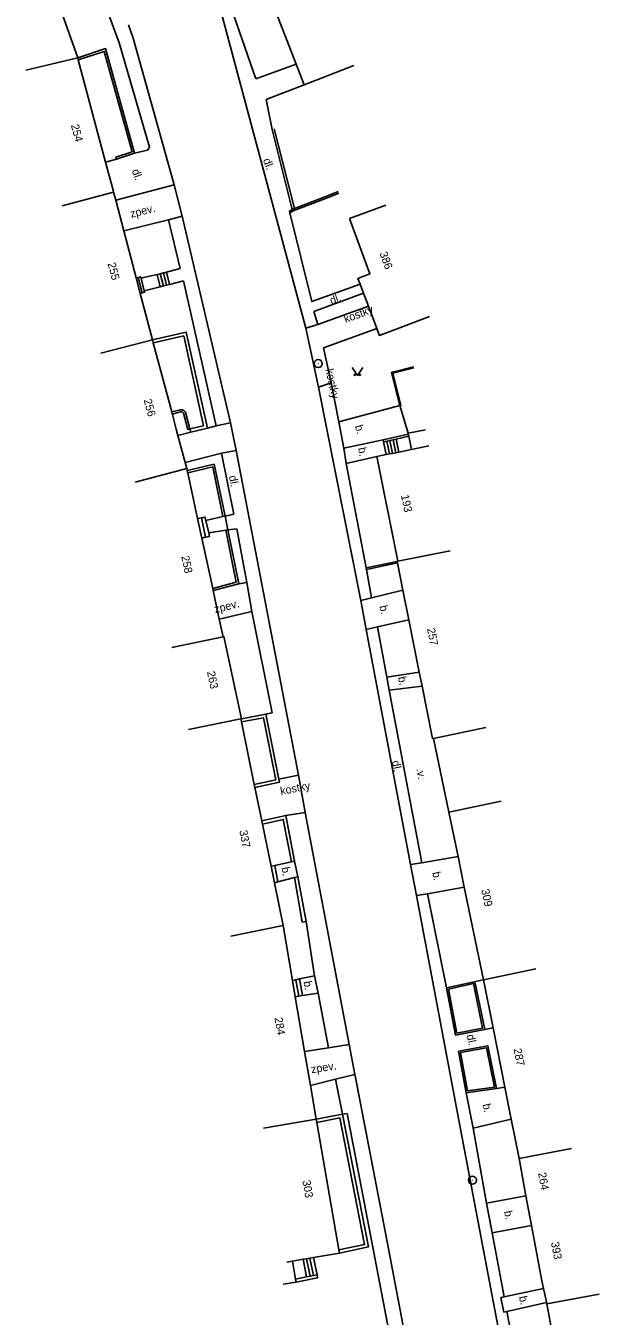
# Model space of a CAD drawing. Extents: x -582162 to -561283, y -1187583 to -1183539.
# Drawn here: x -578230.4 to -578176.6, y -1186277.6 to -1186156.7 of the extents above; entities that cross this region are included whole.
import ezdxf

# ---------------------------------------------------------------- set-up
doc = ezdxf.new("R2010")
doc.units = 0
for name, color, linetype in [('Vrstva 1', 7, 'Continuous'), ('Vrstva 10', 7, 'Continuous'), ('Vrstva 14', 7, 'Continuous'), ('Vrstva 3', 7, 'Continuous'), ('Vrstva 4', 7, 'Continuous'), ('Vrstva 6', 7, 'Continuous'), ('Vrstva 9', 7, 'Continuous')]:
    doc.layers.add(name, color=color, linetype=linetype)

# ---------------------------------------------------------------- blocks, each defined once
blk = doc.blocks.new('1.079')
at = {"layer": 'Vrstva 1'}
for radius in [0.75, 0.001]:
    blk.add_circle((0, -0.001), radius, dxfattribs=at)
blk = doc.blocks.new('3.140')
at = {"layer": 'Vrstva 1'}
blk.add_lwpolyline([(-1, 1.5), (0, 0), (1, 1.5)], dxfattribs=at)
for centre in [(-0.5, 0.1), (0.5, 0.1)]:
    blk.add_circle(centre, 0.1, dxfattribs=at)

msp = doc.modelspace()

# ---------------------------------------------------------------- linework, layer by layer
at = {"layer": 'Vrstva 10'}
for points in [[(-578220.73, -1186156.59), (-578220.31, -1186157.83)], [(-578205.02, -1186160.27), (-578208.79, -1186161.64)], [(-578218.76, -1186168.06), (-578218.95, -1186168.32), (-578220.16, -1186168.61)], [(-578221.86, -1186169.16), (-578222.88, -1186169.45)], [(-578221.94, -1186173.01), (-578216.47, -1186171.59)], [(-578205.62, -1186174.2), (-578205.66, -1186174.04), (-578205.39, -1186173.88)], [(-578199.04, -1186180.88), (-578203.56, -1186182.53), (-578205.62, -1186174.2)], [(-578216.99, -1186174.85), (-578221.18, -1186175.88)], [(-578215.71, -1186174.52), (-578216.99, -1186174.85)], [(-578220.02, -1186180.31), (-578219.83, -1186180.26)], [(-578219.83, -1186180.26), (-578219.6, -1186180.2), (-578219.56, -1186180.34)], [(-578219.83, -1186180.26), (-578219.46, -1186181.71)], [(-578218.05, -1186179.97), (-578219.05, -1186180.2), (-578219.56, -1186180.34)], [(-578217.76, -1186179.91), (-578218.05, -1186179.97)], [(-578217.76, -1186181.13), (-578218.05, -1186179.97)], [(-578217.46, -1186179.84), (-578217.76, -1186179.91)], [(-578217.47, -1186181.06), (-578217.76, -1186179.91)], [(-578217.17, -1186179.77), (-578217.26, -1186179.8), (-578217.46, -1186179.84)], [(-578217.18, -1186180.99), (-578217.46, -1186179.84)], [(-578215.9, -1186179.41), (-578217.17, -1186179.77)], [(-578216.89, -1186180.92), (-578217.17, -1186179.77)], [(-578219.56, -1186180.34), (-578219.27, -1186181.5)], [(-578219.27, -1186181.5), (-578219.23, -1186181.65), (-578219.46, -1186181.71)], [(-578217.76, -1186181.13), (-578219.27, -1186181.5)], [(-578217.47, -1186181.06), (-578217.76, -1186181.13)], [(-578217.18, -1186180.99), (-578217.47, -1186181.06)], [(-578216.89, -1186180.92), (-578217.18, -1186180.99)], [(-578215.57, -1186180.59), (-578216.89, -1186180.92)], [(-578219.46, -1186181.71), (-578219.64, -1186181.76)], [(-578203.01, -1186184.68), (-578203.36, -1186183.46), (-578198.72, -1186181.73)], [(-578198.26, -1186182.94), (-578203.01, -1186184.68)], [(-578203.01, -1186184.68), (-578204.13, -1186185.02)], [(-578197.46, -1186185.06), (-578202.45, -1186186.87), (-578201.74, -1186190.14)], [(-578195.97, -1186189.24), (-578196, -1186189.14)], [(-578201.74, -1186190.14), (-578202.93, -1186190.53)], [(-578201.74, -1186190.14), (-578201.03, -1186193.81)], [(-578195.31, -1186192.26), (-578201.03, -1186193.81)], [(-578194.54, -1186194.86), (-578195.31, -1186192.26)], [(-578214.91, -1186194.75), (-578216.1, -1186195.07)], [(-578212.52, -1186194.18), (-578213.34, -1186194.39)], [(-578211.18, -1186193.9), (-578212.52, -1186194.18)], [(-578201.03, -1186193.81), (-578200.57, -1186196.25)], [(-578196.87, -1186195.47), (-578200.57, -1186196.25)], [(-578196.87, -1186195.47), (-578194.52, -1186194.96)], [(-578196.83, -1186195.67), (-578196.87, -1186195.47)], [(-578196.83, -1186195.67), (-578196.54, -1186195.61)], [(-578196.59, -1186196.87), (-578196.83, -1186195.67)], [(-578196.54, -1186195.61), (-578196.24, -1186195.54)], [(-578196.29, -1186196.81), (-578196.54, -1186195.61)], [(-578196.24, -1186195.54), (-578195.95, -1186195.48)], [(-578196, -1186196.75), (-578196.24, -1186195.54)], [(-578195.95, -1186195.48), (-578195.66, -1186195.41)], [(-578195.7, -1186196.69), (-578195.95, -1186195.48)], [(-578195.66, -1186195.41), (-578194.48, -1186195.15)], [(-578195.41, -1186196.63), (-578195.66, -1186195.41)], [(-578212.01, -1186196.72), (-578215.42, -1186197.6)], [(-578210.64, -1186196.47), (-578212.01, -1186196.72)], [(-578200.57, -1186196.25), (-578200.35, -1186197.71)], [(-578197.48, -1186197.05), (-578200.35, -1186197.71)], [(-578215.42, -1186197.6), (-578215.48, -1186197.61)], [(-578200.35, -1186197.71), (-578198.47, -1186207.49)], [(-578214.26, -1186202.87), (-578213.91, -1186202.79)], [(-578213.91, -1186202.79), (-578213.57, -1186202.72), (-578213.49, -1186203.05)], [(-578213.91, -1186202.79), (-578213.52, -1186204.62)], [(-578211.89, -1186202.68), (-578213.49, -1186203.05)], [(-578213.49, -1186203.05), (-578213.22, -1186204.21)], [(-578210.88, -1186202.44), (-578211.69, -1186202.63)], [(-578213.22, -1186204.21), (-578213.14, -1186204.54), (-578213.52, -1186204.62)], [(-578211.63, -1186203.94), (-578213.22, -1186204.21)], [(-578210.59, -1186203.81), (-578211.43, -1186203.91)], [(-578213.52, -1186204.62), (-578213.87, -1186204.7)], [(-578198.47, -1186207.49), (-578198.44, -1186207.63)], [(-578198.44, -1186207.63), (-578197.96, -1186210.28)], [(-578209.65, -1186208.86), (-578210.41, -1186208.97)], [(-578197.96, -1186210.28), (-578198.97, -1186210.54)], [(-578195.02, -1186209.58), (-578197.96, -1186210.28)], [(-578209.18, -1186211.56), (-578212.23, -1186212.29)], [(-578194.46, -1186212.37), (-578197.41, -1186213.02)], [(-578197.41, -1186213.02), (-578198.47, -1186213.25)], [(-578196.54, -1186217.74), (-578197.41, -1186213.02)], [(-578193.49, -1186217.25), (-578196.54, -1186217.74)], [(-578196.3, -1186218.96), (-578196.54, -1186217.74)], [(-578193.23, -1186218.56), (-578196.3, -1186218.96)], [(-578196.3, -1186218.96), (-578193.26, -1186235.12)], [(-578207.86, -1186221.19), (-578207.27, -1186221.08)], [(-578206.65, -1186227.29), (-578204.81, -1186226.91)], [(-578206, -1186230.7), (-578204.17, -1186230.4)], [(-578193.26, -1186235.12), (-578189.86, -1186234.53)], [(-578207.38, -1186235.46), (-578207.02, -1186235.38)], [(-578207.02, -1186235.38), (-578205.47, -1186235.03)], [(-578207.02, -1186235.38), (-578206.73, -1186236.91)], [(-578205.47, -1186235.03), (-578205.18, -1186234.97)], [(-578204.88, -1186236.45), (-578205.18, -1186234.97)], [(-578194.3, -1186235.3), (-578193.26, -1186235.12)], [(-578207.07, -1186237), (-578206.73, -1186236.91)], [(-578206.73, -1186236.91), (-578205.18, -1186236.52)], [(-578205.18, -1186236.52), (-578204.88, -1186236.45)], [(-578193.75, -1186238.21), (-578192.71, -1186238.04)], [(-578185.27, -1186282.97), (-578189.58, -1186260.25), (-578193.75, -1186238.21)], [(-578192.71, -1186238.04), (-578189.27, -1186237.4)], [(-578204.1, -1186240.62), (-578203.3, -1186245.73)], [(-578205.37, -1186246.16), (-578205.05, -1186246.09)], [(-578205.05, -1186246.09), (-578204.71, -1186246.02)], [(-578205.05, -1186246.09), (-578204.79, -1186247.63)], [(-578204.71, -1186246.02), (-578203.3, -1186245.73)], [(-578204.71, -1186246.02), (-578204.44, -1186247.58)], [(-578202.97, -1186247.36), (-578203.3, -1186245.73)], [(-578190.95, -1186246.84), (-578187.48, -1186246.09)], [(-578205.11, -1186247.68), (-578204.79, -1186247.63)], [(-578204.79, -1186247.63), (-578204.44, -1186247.58)], [(-578204.44, -1186247.58), (-578202.97, -1186247.36)], [(-578202.01, -1186252.47), (-578202.97, -1186247.36)], [(-578187.36, -1186250.76), (-578186.58, -1186250.61)], [(-578204.24, -1186252.82), (-578202.01, -1186252.47)], [(-578202.01, -1186252.47), (-578200.06, -1186252.17)], [(-578201.33, -1186255.42), (-578199.53, -1186254.96)], [(-578203.69, -1186256.02), (-578201.33, -1186255.42)], [(-578200.68, -1186258.7), (-578201.33, -1186255.42)], [(-578200.68, -1186258.7), (-578200.26, -1186258.62)], [(-578187.18, -1186267.05), (-578183.49, -1186266.35)], [(-578186.67, -1186269.83), (-578182.97, -1186269.13)], [(-578204.05, -1186272.24), (-578203.72, -1186273.88)], [(-578203.73, -1186272.19), (-578203.4, -1186273.82)], [(-578203.07, -1186273.75), (-578203.4, -1186272.13)], [(-578204.38, -1186272.3), (-578204.05, -1186273.95)], [(-578205.09, -1186274.16), (-578204.05, -1186273.95)], [(-578205.04, -1186274.43), (-578203.02, -1186274.02), (-578203.07, -1186273.75)], [(-578204.05, -1186273.95), (-578203.72, -1186273.88)], [(-578203.72, -1186273.88), (-578203.4, -1186273.82)], [(-578203.4, -1186273.82), (-578203.07, -1186273.75)], [(-578185.27, -1186277.18), (-578185.57, -1186277.25), (-578185.84, -1186275.88), (-578185.54, -1186275.81)], [(-578185.54, -1186275.81), (-578181.85, -1186275.04)], [(-578181.56, -1186276.36), (-578185.27, -1186277.18)], [(-578184.2, -1186282.8), (-578185.27, -1186277.18)]]:
    msp.add_lwpolyline(points, dxfattribs=at)
at = {"layer": 'Vrstva 4'}
for points in [[(-578205.02, -1186160.27), (-578208.41, -1186151.54)], [(-578227.12, -1186155.11), (-578225.5, -1186159.67)], [(-578225.5, -1186159.67), (-578230.36, -1186160.84)], [(-578225.5, -1186159.67), (-578225.45, -1186159.86)], [(-578225.45, -1186159.86), (-578222.88, -1186169.45)], [(-578204.27, -1186162.2), (-578205.02, -1186160.27)], [(-578199.61, -1186160.39), (-578204.27, -1186162.2)], [(-578222.88, -1186169.45), (-578222.18, -1186172.08)], [(-578226.96, -1186173.56), (-578222.13, -1186172.27)], [(-578222.18, -1186172.08), (-578222.13, -1186172.27)], [(-578222.13, -1186172.27), (-578221.94, -1186173.01)], [(-578221.94, -1186173.01), (-578221.18, -1186175.88)], [(-578199.15, -1186180.58), (-578199.24, -1186180.35), (-578198.12, -1186179.93), (-578200.02, -1186174.75), (-578196.63, -1186173.5)], [(-578221.18, -1186175.88), (-578220.02, -1186180.31)], [(-578220.02, -1186180.31), (-578219.64, -1186181.76)], [(-578199.04, -1186180.88), (-578199.15, -1186180.58)], [(-578198.72, -1186181.73), (-578199.04, -1186180.88)], [(-578219.64, -1186181.76), (-578218.5, -1186186.1)], [(-578198.26, -1186182.94), (-578198.72, -1186181.73)], [(-578197.46, -1186185.06), (-578198.26, -1186182.94)], [(-578192.54, -1186183.93), (-578197.22, -1186185.7), (-578197.31, -1186185.47)], [(-578197.31, -1186185.47), (-578197.46, -1186185.06)], [(-578223.34, -1186187.37), (-578218.5, -1186186.1)], [(-578218.5, -1186186.1), (-578218.42, -1186186.39)], [(-578218.42, -1186186.39), (-578216.68, -1186192.87)], [(-578216.68, -1186192.87), (-578216.63, -1186193.07)], [(-578216.63, -1186193.07), (-578216.62, -1186193.12)], [(-578216.62, -1186193.12), (-578216.26, -1186194.48)], [(-578216.26, -1186194.48), (-578216.1, -1186195.07)], [(-578194.54, -1186194.86), (-578192.92, -1186194.53)], [(-578216.1, -1186195.07), (-578215.42, -1186197.6)], [(-578194.52, -1186194.96), (-578194.54, -1186194.86)], [(-578194.48, -1186195.15), (-578194.52, -1186194.96)], [(-578194.23, -1186196.39), (-578194.48, -1186195.15)], [(-578194.23, -1186196.39), (-578192.58, -1186196.06)], [(-578197.48, -1186197.05), (-578196.59, -1186196.87)], [(-578195.49, -1186206.87), (-578197.48, -1186197.05)], [(-578196.59, -1186196.87), (-578196.29, -1186196.81)], [(-578196.29, -1186196.81), (-578196, -1186196.75)], [(-578196, -1186196.75), (-578195.7, -1186196.69)], [(-578195.7, -1186196.69), (-578195.41, -1186196.63)], [(-578195.41, -1186196.63), (-578194.23, -1186196.39)], [(-578220.1, -1186199.46), (-578215.27, -1186198.17)], [(-578215.42, -1186197.6), (-578215.27, -1186198.17)], [(-578215.23, -1186198.37), (-578215.27, -1186198.17)], [(-578215.19, -1186198.56), (-578215.23, -1186198.37)], [(-578214.26, -1186202.87), (-578215.19, -1186198.56)], [(-578213.87, -1186204.7), (-578214.26, -1186202.87)], [(-578212.85, -1186209.41), (-578213.87, -1186204.7)], [(-578195.56, -1186206.88), (-578195.49, -1186206.87)], [(-578195.53, -1186207.02), (-578195.56, -1186206.88)], [(-578190.59, -1186205.88), (-578195.49, -1186206.87)], [(-578195.02, -1186209.58), (-578195.53, -1186207.02)], [(-578212.81, -1186209.6), (-578212.85, -1186209.41)], [(-578212.23, -1186212.29), (-578212.81, -1186209.6)], [(-578194.46, -1186212.37), (-578195.02, -1186209.58)], [(-578211.88, -1186213.94), (-578212.23, -1186212.29)], [(-578193.49, -1186217.25), (-578194.46, -1186212.37)], [(-578216.68, -1186214.96), (-578211.88, -1186213.94)], [(-578211.88, -1186213.94), (-578211.79, -1186213.92), (-578210.15, -1186221.63)], [(-578193.23, -1186218.56), (-578193.49, -1186217.25)], [(-578192.15, -1186223.47), (-578192.24, -1186223.49), (-578193.23, -1186218.56)], [(-578215.1, -1186222.64), (-578210.2, -1186221.64)], [(-578210.15, -1186221.63), (-578210.2, -1186221.64)], [(-578210.2, -1186221.64), (-578210.14, -1186221.93)], [(-578210.14, -1186221.93), (-578208.95, -1186227.78)], [(-578187.25, -1186222.45), (-578192.15, -1186223.47)], [(-578192.15, -1186223.47), (-578190.71, -1186230.37)], [(-578208.95, -1186227.78), (-578208.89, -1186228.08)], [(-578208.89, -1186228.08), (-578208.25, -1186231.21)], [(-578185.81, -1186229.36), (-578190.71, -1186230.37)], [(-578189.86, -1186234.53), (-578190.71, -1186230.37)], [(-578208.25, -1186231.21), (-578208.19, -1186231.5)], [(-578208.19, -1186231.5), (-578207.38, -1186235.46)], [(-578189.27, -1186237.4), (-578189.86, -1186234.53)], [(-578207.38, -1186235.46), (-578207.07, -1186237)], [(-578207.07, -1186237), (-578206.25, -1186241.02)], [(-578187.48, -1186246.09), (-578189.27, -1186237.4)], [(-578211.15, -1186242.02), (-578206.25, -1186241.02)], [(-578205.37, -1186246.16), (-578206.25, -1186241.02)], [(-578182.58, -1186245.08), (-578187.48, -1186246.09)], [(-578205.11, -1186247.68), (-578205.37, -1186246.16)], [(-578186.58, -1186250.61), (-578187.48, -1186246.09)], [(-578204.24, -1186252.82), (-578205.11, -1186247.68)], [(-578185.47, -1186256.17), (-578186.58, -1186250.61)], [(-578203.69, -1186256.02), (-578204.24, -1186252.82)], [(-578203.15, -1186259.17), (-578203.69, -1186256.02)], [(-578184.87, -1186259.17), (-578185.47, -1186256.17)], [(-578208.08, -1186260.01), (-578203.15, -1186259.17)], [(-578203.1, -1186259.46), (-578203.15, -1186259.17)], [(-578201.03, -1186271.42), (-578203.1, -1186259.46)], [(-578184.14, -1186262.84), (-578184.87, -1186259.17)], [(-578179.23, -1186261.9), (-578184.14, -1186262.84)], [(-578183.49, -1186266.35), (-578184.14, -1186262.84)], [(-578182.97, -1186269.13), (-578183.49, -1186266.35)], [(-578182.01, -1186274.31), (-578182.97, -1186269.13)], [(-578204.38, -1186272.3), (-578204.05, -1186272.24)], [(-578204.05, -1186272.24), (-578203.73, -1186272.19)], [(-578203.73, -1186272.19), (-578203.4, -1186272.13)], [(-578203.4, -1186272.13), (-578200.98, -1186271.71)], [(-578200.98, -1186271.71), (-578201.03, -1186271.42)], [(-578205.91, -1186272.56), (-578205.38, -1186272.47)], [(-578205.38, -1186272.47), (-578204.38, -1186272.3)], [(-578205.38, -1186272.47), (-578205.09, -1186274.16)], [(-578205.04, -1186274.43), (-578206.23, -1186274.64)], [(-578205.09, -1186274.16), (-578205.04, -1186274.43)], [(-578181.85, -1186275.04), (-578182.01, -1186274.31)], [(-578181.61, -1186276.14), (-578181.85, -1186275.04)], [(-578176.63, -1186275.56), (-578181.54, -1186276.48)], [(-578181.56, -1186276.36), (-578181.61, -1186276.14)], [(-578181.54, -1186276.48), (-578181.56, -1186276.36)], [(-578180.47, -1186282.21), (-578181.54, -1186276.48)]]:
    msp.add_lwpolyline(points, dxfattribs=at)
at = {"layer": 'Vrstva 9'}
for points in [[(-578216.21, -1186143.83), (-578212.61, -1186153.27), (-578204.13, -1186185.02)], [(-578214.67, -1186144.7), (-578208.79, -1186161.64)], [(-578218.76, -1186168.06), (-578221.6, -1186158.27), (-578223.26, -1186153.75)], [(-578216.47, -1186171.59), (-578220.31, -1186157.83)], [(-578220.16, -1186168.61), (-578222.88, -1186158.81), (-578225.5, -1186159.67)], [(-578225.45, -1186159.86), (-578223.02, -1186159.07), (-578220.4, -1186168.48), (-578221.92, -1186168.97), (-578221.86, -1186169.16)], [(-578204.27, -1186162.2), (-578207.83, -1186163.58)], [(-578205.39, -1186173.88), (-578207.28, -1186166.38), (-578207.83, -1186163.58)], [(-578207.08, -1186166.33), (-578205.19, -1186173.8)], [(-578220.16, -1186168.61), (-578221.86, -1186169.16)], [(-578215.71, -1186174.52), (-578216.47, -1186171.59)], [(-578205.62, -1186174.2), (-578205.32, -1186174.03), (-578202.18, -1186172.83), (-578201.04, -1186172.36)], [(-578205.19, -1186173.8), (-578202.24, -1186172.68)], [(-578202.24, -1186172.68), (-578201.1, -1186172.21)], [(-578205.39, -1186173.88), (-578205.19, -1186173.8)], [(-578215.9, -1186179.41), (-578216.99, -1186174.85)], [(-578211.18, -1186193.9), (-578215.71, -1186174.52)], [(-578212.52, -1186194.18), (-578215.57, -1186180.59)], [(-578204.13, -1186185.02), (-578202.93, -1186190.53)], [(-578213.34, -1186194.39), (-578215.33, -1186185.38), (-578218.5, -1186186.1)], [(-578214.99, -1186194.46), (-578213.7, -1186194.16), (-578215.56, -1186185.74), (-578218.42, -1186186.39)], [(-578196, -1186189.14), (-578194.02, -1186188.64)], [(-578194, -1186188.73), (-578195.97, -1186189.24)], [(-578195.31, -1186192.26), (-578196.1, -1186189.17), (-578196, -1186189.14)], [(-578195.31, -1186192.26), (-578195.21, -1186192.24), (-578195.97, -1186189.24)], [(-578202.93, -1186190.53), (-578198.97, -1186210.54)], [(-578214.99, -1186194.46), (-578215.4, -1186192.9), (-578215.52, -1186192.75), (-578215.68, -1186192.67), (-578215.87, -1186192.66), (-578216.68, -1186192.87)], [(-578214.99, -1186194.46), (-578215.18, -1186194.5), (-578215.58, -1186192.99), (-578215.67, -1186192.89), (-578215.8, -1186192.85), (-578215.85, -1186192.86), (-578216.63, -1186193.07)], [(-578214.91, -1186194.75), (-578214.99, -1186194.46)], [(-578213.34, -1186194.39), (-578214.91, -1186194.75)], [(-578210.64, -1186196.47), (-578211.18, -1186193.9)], [(-578210.88, -1186202.44), (-578212.01, -1186196.72)], [(-578204.81, -1186226.91), (-578210.64, -1186196.47)], [(-578215.23, -1186198.37), (-578212.7, -1186197.76)], [(-578215.19, -1186198.56), (-578212.85, -1186198)], [(-578212.85, -1186198), (-578211.89, -1186202.68)], [(-578212.7, -1186197.76), (-578211.69, -1186202.63)], [(-578211.69, -1186202.63), (-578211.89, -1186202.68)], [(-578211.69, -1186202.63), (-578211.43, -1186203.91)], [(-578211.43, -1186203.91), (-578211.63, -1186203.94)], [(-578211.63, -1186203.94), (-578210.64, -1186208.82)], [(-578211.43, -1186203.91), (-578210.41, -1186208.97)], [(-578209.65, -1186208.86), (-578210.59, -1186203.81)], [(-578195.56, -1186206.88), (-578198.47, -1186207.49)], [(-578195.53, -1186207.02), (-578198.44, -1186207.63)], [(-578210.64, -1186208.82), (-578212.85, -1186209.41)], [(-578210.41, -1186208.97), (-578212.81, -1186209.6)], [(-578209.18, -1186211.56), (-578209.65, -1186208.86)], [(-578198.97, -1186210.54), (-578198.47, -1186213.25)], [(-578207.27, -1186221.08), (-578209.18, -1186211.56)], [(-578198.47, -1186213.25), (-578194.3, -1186235.3)], [(-578210.15, -1186221.63), (-578207.86, -1186221.19)], [(-578207.86, -1186221.19), (-578206.65, -1186227.29)], [(-578208.95, -1186227.78), (-578206.94, -1186227.35), (-578208.1, -1186221.54), (-578210.14, -1186221.93)], [(-578208.89, -1186228.08), (-578206.59, -1186227.58), (-578206.65, -1186227.29)], [(-578204.17, -1186230.4), (-578204.81, -1186226.91)], [(-578208.25, -1186231.21), (-578206, -1186230.7)], [(-578205.47, -1186235.03), (-578206.24, -1186231.06), (-578208.19, -1186231.5)], [(-578205.18, -1186234.97), (-578206, -1186230.7)], [(-578200.06, -1186252.17), (-578200.18, -1186251.52), (-578204.17, -1186230.4)], [(-578194.3, -1186235.3), (-578193.75, -1186238.21)], [(-578204.1, -1186240.62), (-578204.46, -1186240.68), (-578205.18, -1186236.52)], [(-578204.88, -1186236.45), (-578204.1, -1186240.62)], [(-578192.71, -1186238.04), (-578190.95, -1186246.84)], [(-578190.95, -1186246.84), (-578190.09, -1186251.3)], [(-578190.76, -1186246.96), (-578188.42, -1186246.45)], [(-578189.96, -1186251.11), (-578187.55, -1186250.63), (-578188.42, -1186246.45)], [(-578188.42, -1186246.45), (-578188.26, -1186246.42), (-578187.36, -1186250.76)], [(-578190.76, -1186246.96), (-578189.96, -1186251.11)], [(-578190.09, -1186251.3), (-578187.36, -1186250.76)], [(-578199.53, -1186254.96), (-578200.06, -1186252.17)], [(-578189.82, -1186252.78), (-578187.05, -1186252.3), (-578186.24, -1186256.28)], [(-578189.82, -1186252.78), (-578189.09, -1186256.69)], [(-578189.64, -1186252.91), (-578187.18, -1186252.48), (-578186.43, -1186256.15)], [(-578189.64, -1186252.91), (-578188.96, -1186256.51), (-578186.43, -1186256.15)], [(-578191.2, -1186298.6), (-578196.47, -1186270.83), (-578199.51, -1186255.09), (-578199.53, -1186254.96)], [(-578186.24, -1186256.28), (-578189.09, -1186256.69)], [(-578185.47, -1186256.17), (-578186.24, -1186256.28)], [(-578189.09, -1186256.69), (-578188.44, -1186260)], [(-578203.15, -1186259.17), (-578200.68, -1186258.7)], [(-578200.98, -1186271.71), (-578198.26, -1186271.14), (-578200.68, -1186258.7)], [(-578192.53, -1186298.88), (-578200.26, -1186258.62)], [(-578203.1, -1186259.46), (-578200.92, -1186259.05), (-578198.61, -1186270.91), (-578201.03, -1186271.42)], [(-578184.87, -1186259.17), (-578188.44, -1186260)], [(-578188.44, -1186260), (-578187.18, -1186267.05)], [(-578187.18, -1186267.05), (-578186.67, -1186269.83)], [(-578186.67, -1186269.83), (-578185.54, -1186275.81)]]:
    msp.add_lwpolyline(points, dxfattribs=at)

# ---------------------------------------------------------------- block references
at = {"layer": 'Vrstva 1', "xscale": 0.5, "yscale": 0.5}
for p in [(-578202.96, -1186188.34), (-578188.51, -1186264.88)]:
    msp.add_blockref('1.079', p, dxfattribs=at)
at = {"layer": 'Vrstva 3', "xscale": 0.5, "yscale": 0.5}
msp.add_blockref('3.140', (-578199.29, -1186189.45), dxfattribs=at)

# ---------------------------------------------------------------- texts
at = {"layer": 'Vrstva 14'}
for s, rotation, p in [('dl.', 290.863, (-578208.15, -1186169.25)), ('dl.', 289.526, (-578220.44, -1186170.24)), ('zpev.', 14.51, (-578220.48, -1186174.68)), ('dl.', 20.506, (-578201.71, -1186182.82)), ('kostky', 20.506, (-578200.39, -1186184.54)), ('kostky', 282.25, (-578202.28, -1186188.9)), ('b.', 286.497, (-578199.53, -1186194.2)), ('b.', 281.303, (-578199.23, -1186196.26)), ('dl.', 280.842, (-578211.33, -1186198.9)), ('zpev.', 14.697, (-578212.6, -1186211.75)), ('b.', 281.303, (-578197.22, -1186211.07)), ('b.', 281.303, (-578195.49, -1186217.74)), ('dl.', 281.303, (-578196.06, -1186225.62)), ('.v.', 279.506, (-578193.76, -1186226.32)), ('kostky', 11.283, (-578206.44, -1186228.78)), ('b.', 280.238, (-578206.41, -1186235.59)), ('b.', 281.653, (-578192.27, -1186236.04)), ('b.', 280.238, (-578204.34, -1186246.28)), ('dl.', 281.653, (-578189.06, -1186251.29)), ('zpev.', 8.818, (-578203.57, -1186254.86)), ('b.', 281.653, (-578187.55, -1186257.78)), ('b.', 281.653, (-578185.55, -1186267.82)), ('b.', 281.653, (-578184.15, -1186275.81))]:
    msp.add_text(s, height=0.75, rotation=rotation, dxfattribs=at).set_placement(p)
at = {"layer": 'Vrstva 6'}
for s, rotation, p in [('254', 284.974, (-578226.14, -1186166)), ('386', 290.186, (-578197.23, -1186178)), ('255', 284.707, (-578222.7, -1186178.96)), ('256', 284.982, (-578219.32, -1186191.75)), ('193', 281.456, (-578195.21, -1186200.69)), ('258', 282.141, (-578215.8, -1186206.42)), ('257', 281.303, (-578192.77, -1186213.19)), ('263', 282.008, (-578213.39, -1186217.24)), ('337', 281.517, (-578210.36, -1186232.14)), ('309', 281.611, (-578187.68, -1186237.66)), ('284', 279.693, (-578207.06, -1186249.67)), ('287', 281.277, (-578184.66, -1186252.59)), ('303', 279.818, (-578204.44, -1186264.94)), ('264', 280.52, (-578182.36, -1186264.22)), ('393', 280.52, (-578181.15, -1186270.72))]:
    msp.add_text(s, height=0.75, rotation=rotation, dxfattribs=at).set_placement(p)

doc.saveas('drawing.dxf')
